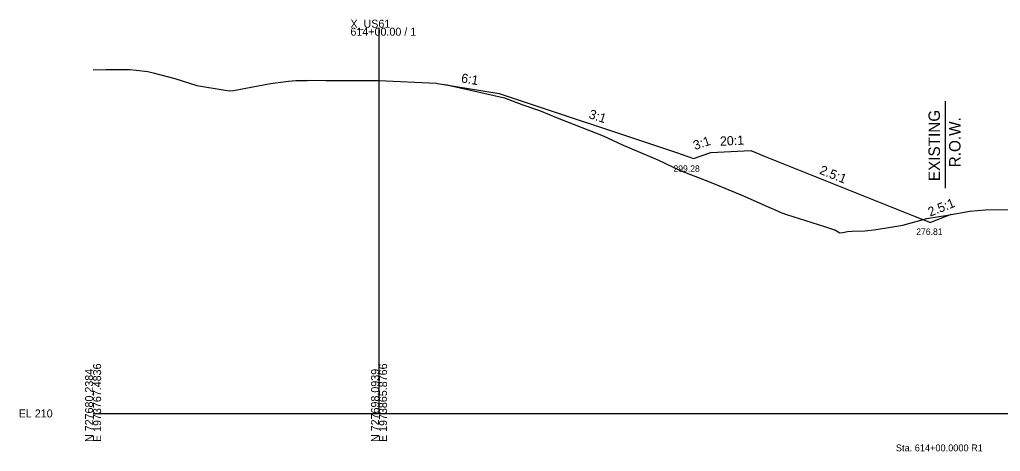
# Model space of a CAD drawing. Extents: x -26 to 1604, y -13 to 9623.
# Drawn here: x -25.7 to 317.3, y 4986.7 to 5137.8 of the extents above; entities that cross this region are included whole.
import ezdxf

# ---------------------------------------------------------------- set-up
doc = ezdxf.new("R2010")
doc.units = 0
for name, color, linetype in [('Draft_XS_Grid', 7, 'Continuous'), ('Draft_XS_Text', 7, 'Continuous'), ('DTM_X_GROUND', 7, 'Continuous'), ('SLOPE_STAKES_FILL', 7, 'Continuous'), ('XS_CELL', 7, 'Continuous'), ('XS_P_GROUND', 7, 'Continuous'), ('XS_P_TX_DCH', 7, 'Continuous'), ('XS_P_TX_FS_BS', 7, 'Continuous'), ('XS_X_ROW', 7, 'Continuous')]:
    doc.layers.add(name, color=color, linetype=linetype)

msp = doc.modelspace()

# ---------------------------------------------------------------- linework, layer by layer
at = {"layer": 'DTM_X_GROUND'}
msp.add_lwpolyline([(0, 5120.29), (4.46, 5120.37), (11.46, 5120.37), (12.88, 5120.37), (15.04, 5120.13), (19.16, 5119.67), (20.99, 5119.21), (28.58, 5117.22), (36.25, 5114.72), (46.25, 5113.12), (47.65, 5112.89), (49.14, 5113.06), (61.99, 5115.46), (68.33, 5116.3), (70.87, 5116.51), (74.84, 5116.58), (75.62, 5116.59), (81.42, 5116.56), (96.25, 5116.49), (99.92, 5116.47), (120.05, 5115.54), (120.34, 5115.53), (120.39, 5115.52), (123.85, 5115), (124.8, 5114.79), (143.89, 5110.47), (150.34, 5108.06), (156.11, 5106.02), (162.86, 5103.23), (178.39, 5097.16), (185.34, 5093.86), (197.56, 5088.79), (205.26, 5085.07), (215.59, 5081.1), (227.72, 5076.08), (236.34, 5072.21), (237.99, 5071.44), (240.85, 5070.17), (242.46, 5069.63), (255.78, 5065.42), (259.33, 5064.25), (259.35, 5064.25), (261.1, 5063.21), (262.15, 5063.38), (263.8, 5063.66), (265.5, 5063.74), (269.96, 5063.95), (273.91, 5064.4), (283.17, 5065.94), (291.63, 5068.18), (298.84, 5069.45), (306.66, 5070.8), (312.01, 5071.23), (321.32, 5071.43)], dxfattribs=at)
at = {"layer": 'XS_CELL'}
for p, q in [((100, 5000), (100, 5135)), ((0, 5000), (100, 5000)), ((100, 5000), (600, 5000))]:
    msp.add_line(p, q, dxfattribs=at)
at = {"layer": 'XS_P_GROUND'}
for points in [[(122, 5115.28), (142, 5111.95)], [(142, 5111.95), (204, 5091.28), (210, 5089.28), (216, 5091.28), (230, 5091.98), (235, 5089.98)], [(235, 5089.98), (286.91, 5069.21), (292.91, 5066.81)], [(300.01, 5069.65), (300, 5069.65), (298.91, 5069.21), (298.77, 5069.16), (292.91, 5066.81)]]:
    msp.add_lwpolyline(points, dxfattribs=at)
at = {"layer": 'XS_X_ROW'}
msp.add_line((298, 5109.34), (298, 5078.79), dxfattribs=at)

# ---------------------------------------------------------------- texts
at = {"layer": 'Draft_XS_Grid'}
msp.add_text('-', height=0.0001, dxfattribs=at).set_placement((0, 5000))
at = {"layer": 'Draft_XS_Text'}
msp.add_text('Sta. 614+00.0000 R1', height=2.4, dxfattribs=at).set_placement((280.75, 4986.75))
at = {"layer": 'SLOPE_STAKES_FILL'}
for p in [(141.96, 5111.89), (203.96, 5091.22), (215.96, 5091.22), (229.96, 5091.92), (209.96, 5089.22), (299.97, 5069.59), (286.87, 5069.15), (292.87, 5066.75), (298.87, 5069.15)]:
    msp.add_text('X', height=0.12, dxfattribs=at).set_placement(p)
at = {"layer": 'XS_CELL'}
for s, p in [('X_US61', (90, 5135)), ('614+00.00 / 1', (90, 5132.2)), ('EL 210', (-26, 4998.6))]:
    msp.add_text(s, height=2.8, dxfattribs=at).set_placement(p)
for s, p in [('N 727680.2384', (0, 4990)), ('E 1973767.4836', (2.8, 4990)), ('N 727698.0939', (100, 4990)), ('E 1973865.8766', (102.8, 4990))]:
    msp.add_text(s, height=2.8, rotation=90, dxfattribs=at).set_placement(p)
at = {"layer": 'XS_P_GROUND'}
for p in [(121.96, 5115.22), (234.96, 5089.92)]:
    msp.add_text('X', height=0.12, dxfattribs=at).set_placement(p)
at = {"layer": 'XS_P_TX_DCH'}
for s, p in [('299.28', (202.96, 5084.57)), ('276.81', (287.87, 5062.49))]:
    msp.add_text(s, height=2.25, dxfattribs=at).set_placement(p)
at = {"layer": 'XS_P_TX_FS_BS'}
for s, rotation, p in [('6:1', 350.5377, (128.55, 5115.89)), ('3:1', 341.5651, (173.11, 5103.44)), ('20:1', 2.8624, (219.31, 5093.66)), ('3:1', 18.4349, (210.51, 5092.17)), ('2.5:1', 338.1986, (253.77, 5083.97)), ('2.5:1', 21.8014, (292.74, 5068.85))]:
    msp.add_text(s, height=3.24, rotation=rotation, dxfattribs=at).set_placement(p)
at = {"layer": 'XS_X_ROW'}
for s, p in [('EXISTING', (296.16, 5081.31)), ('R.O.W.', (303.36, 5086.15))]:
    msp.add_text(s, height=4, rotation=90, dxfattribs=at).set_placement(p)

doc.saveas('drawing.dxf')
